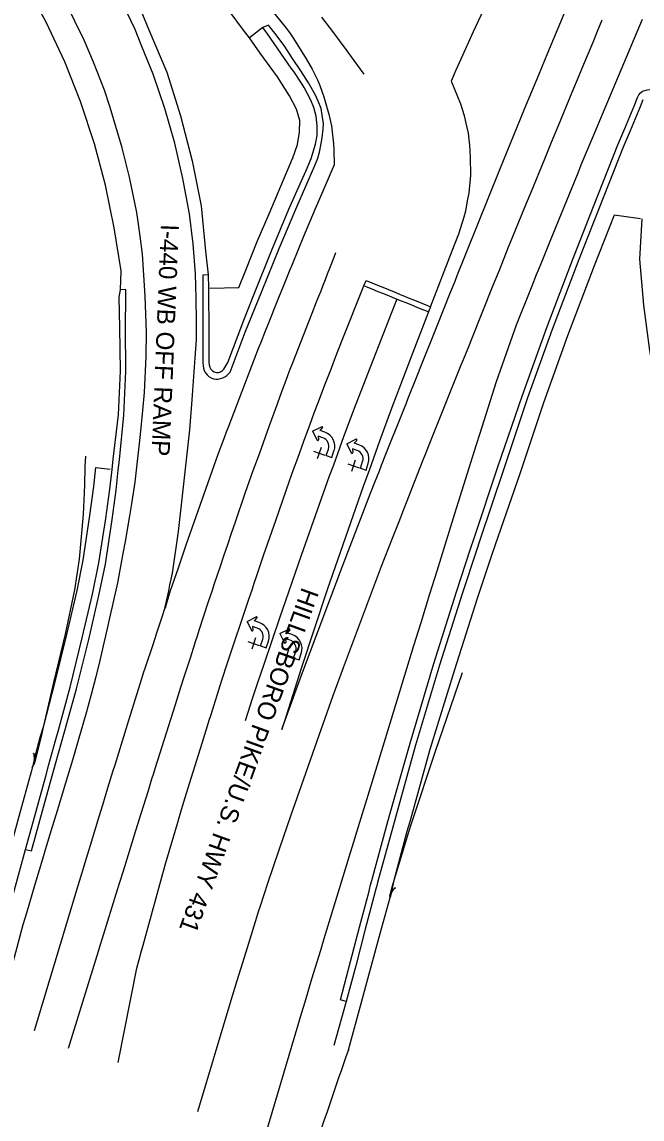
# Model space of a CAD drawing. Extents: x 1729281 to 1732101, y 650763 to 653805.
# Drawn here: x 1730319.8 to 1730526, y 652586.3 to 652950.8 of the extents above; entities that cross this region are included whole.
import ezdxf

# ---------------------------------------------------------------- set-up
doc = ezdxf.new("R2010")
doc.units = 0
for name, color, linetype in [('SURVEY - ROADSIDE BARRIERS with Text', 7, 'Continuous'), ('SURVEY - TRAFFIC CONTROL - Pavement Marking - Points - Locators', 7, 'Continuous'), ('SURVEY - TRAFFIC CONTROL - Pavement Marking with Text', 7, 'Continuous'), ('SURVEY - TRANSPORTATION - Features', 7, 'Continuous'), ('SURVEY - TRANSPORTATION - Roads', 7, 'Continuous'), ('SURVEY - TRANSPORTATION - Roads Text', 7, 'Continuous')]:
    doc.layers.add(name, color=color, linetype=linetype)

msp = doc.modelspace()

# ---------------------------------------------------------------- linework, layer by layer
at = {"layer": 'SURVEY - ROADSIDE BARRIERS with Text'}
for p, q in [((1730323.48, 652707.85), (1730323.81, 652707.7)), ((1730323.28, 652703.06), (1730323.77, 652703.93))]:
    msp.add_line(p, q, dxfattribs=at)
for points in [[(1730317.03, 652661.21), (1730321.04, 652675.83), (1730323.65, 652685.33), (1730327.77, 652700.22), (1730328.82, 652704.05), (1730331.03, 652712), (1730332.04, 652715.52), (1730335.89, 652729.8), (1730339.91, 652746.11), (1730343.31, 652760.69), (1730345.43, 652771.07), (1730347.71, 652785.85), (1730349.04, 652795.59), (1730349.79, 652802.13), (1730350.2, 652805.52), (1730351.91, 652820.29), (1730352.55, 652834.89), (1730352.42, 652849.23), (1730352.17, 652859.39), (1730352.6, 652861.75), (1730352.77, 652868.11), (1730350.46, 652882.38), (1730347.64, 652896.54), (1730343.94, 652910.3), (1730339.31, 652924.42), (1730334.05, 652937.55), (1730327.89, 652950.76), (1730321.01, 652963.38)], [(1730340.94, 652806.57), (1730340.78, 652803.16), (1730340.61, 652796.87), (1730340.24, 652787.16), (1730338.91, 652772.25), (1730337.28, 652762.07), (1730334.19, 652747.41), (1730330.32, 652731.28), (1730327.01, 652716.98), (1730326.18, 652713.41), (1730324.22, 652705.45), (1730323.77, 652703.93)], [(1730442.21, 652659.85), (1730442.15, 652660.49), (1730442.56, 652661.96), (1730442.96, 652663.41), (1730448.42, 652681.69), (1730449.44, 652684.86), (1730457.36, 652708.51), (1730466.35, 652734.7)], [(1730323.81, 652707.7), (1730323.87, 652705.55), (1730322.94, 652701.68), (1730318.83, 652686.79), (1730312.19, 652662.65), (1730309.57, 652652.97)], [(1730428.35, 652609.31), (1730432.4, 652623.88), (1730438.97, 652647.88), (1730442.21, 652659.85), (1730442.35, 652660.43), (1730442.97, 652661.84), (1730443.86, 652663.13), (1730444.13, 652663.12)]]:
    msp.add_lwpolyline(points, dxfattribs=at)
msp.add_spline([(1730428.35, 652609.31), (1730415.72, 652571.98), (1730403.87, 652531.63), (1730394.24, 652490.63), (1730385.26, 652449.43), (1730380.52, 652428.91), (1730375.36, 652408.51), (1730367.56, 652381.34), (1730359.22, 652354.31), (1730350.97, 652327.24), (1730343.49, 652299.92), (1730331.76, 652236.06), (1730325.69, 652182.09), (1730325.22, 652171.48), (1730325.45, 652160.84), (1730326.25, 652150.19), (1730327.47, 652139.56), (1730328.99, 652131.02), (1730331.3, 652122.71), (1730334.46, 652114.6), (1730338.55, 652106.68), (1730353.24, 652086.17), (1730370.71, 652068.21), (1730383.64, 652057.01), (1730397.86, 652047.48), (1730417.53, 652038.47), (1730438.22, 652032.47), (1730458.04, 652029.27), (1730477.86, 652028.54), (1730498.82, 652030.45), (1730519.65, 652035.69), (1730535.91, 652042.78), (1730550.86, 652052.24), (1730565.16, 652063.87), (1730577.86, 652077.14), (1730589.3, 652092.39), (1730598.41, 652109.02), (1730609.65, 652143.27), (1730613.44, 652158.99), (1730614.54, 652166.87), (1730614.65, 652174.72), (1730612.2, 652191.35), (1730608.22, 652207.96), (1730604.12, 652224.02), (1730598.94, 652239.77), (1730589.94, 652257.05), (1730578.5, 652272.95), (1730563.61, 652291.16), (1730547.07, 652307.62), (1730534.67, 652317.36), (1730521.92, 652326.37), (1730495.28, 652342.65), (1730480.87, 652350.64), (1730466.34, 652358.38), (1730436.7, 652372.67), (1730372.96, 652400.09)], degree=3, dxfattribs=at)
at = {"layer": 'SURVEY - TRAFFIC CONTROL - Pavement Marking - Points - Locators'}
for p, q in [((1730416.76, 652808.15), (1730420.55, 652806.86)), ((1730419.29, 652809.4), (1730418.01, 652805.61)), ((1730428.14, 652803.96), (1730431.93, 652802.68)), ((1730430.67, 652805.21), (1730429.39, 652801.43)), ((1730394.96, 652744.92), (1730398.75, 652743.64)), ((1730397.5, 652746.17), (1730396.22, 652742.38)), ((1730405.88, 652740.88), (1730409.67, 652739.6)), ((1730408.41, 652742.13), (1730407.13, 652738.34))]:
    msp.add_line(p, q, dxfattribs=at)
at = {"layer": 'SURVEY - TRAFFIC CONTROL - Pavement Marking with Text'}
for p, q in [((1730416.45, 652814.83), (1730419.48, 652816.32)), ((1730416.45, 652814.83), (1730417.95, 652811.8)), ((1730419.87, 652812.63), (1730418.34, 652813.15)), ((1730418.34, 652813.15), (1730418.42, 652811.93)), ((1730418.96, 652815.02), (1730419.77, 652815.94)), ((1730420.5, 652814.5), (1730418.96, 652815.02)), ((1730427.83, 652810.64), (1730430.86, 652812.14)), ((1730427.83, 652810.64), (1730429.33, 652807.61)), ((1730430.34, 652810.83), (1730431.15, 652811.76)), ((1730431.88, 652810.31), (1730430.34, 652810.83)), ((1730420.98, 652806.72), (1730421.72, 652808.89)), ((1730420.98, 652806.72), (1730422.85, 652806.09)), ((1730422.85, 652806.09), (1730423.58, 652808.26)), ((1730431.25, 652808.45), (1730429.71, 652808.97)), ((1730429.71, 652808.97), (1730429.8, 652807.74)), ((1730432.36, 652802.53), (1730433.1, 652804.71)), ((1730432.36, 652802.53), (1730434.23, 652801.9)), ((1730434.23, 652801.9), (1730434.96, 652804.08)), ((1730394.66, 652751.6), (1730397.68, 652753.1)), ((1730394.66, 652751.6), (1730396.15, 652748.57)), ((1730397.17, 652751.79), (1730397.98, 652752.72)), ((1730398.7, 652751.27), (1730397.17, 652751.79)), ((1730398.07, 652749.41), (1730396.54, 652749.92)), ((1730396.54, 652749.92), (1730396.62, 652748.7)), ((1730405.57, 652747.56), (1730408.6, 652749.06)), ((1730405.57, 652747.56), (1730407.07, 652744.53)), ((1730408.08, 652747.75), (1730408.89, 652748.67)), ((1730409.62, 652747.23), (1730408.08, 652747.75)), ((1730399.19, 652743.49), (1730399.92, 652745.67)), ((1730401.05, 652742.86), (1730401.79, 652745.04)), ((1730408.99, 652745.37), (1730407.45, 652745.88)), ((1730407.45, 652745.88), (1730407.54, 652744.66)), ((1730399.19, 652743.49), (1730401.05, 652742.86)), ((1730410.1, 652739.45), (1730410.84, 652741.62)), ((1730411.97, 652738.82), (1730412.7, 652741)), ((1730410.1, 652739.45), (1730411.97, 652738.82))]:
    msp.add_line(p, q, dxfattribs=at)
for points in [[(1730462.6, 652931.2), (1730464.23, 652934.85), (1730465.86, 652938.5), (1730469.98, 652947.59), (1730475.83, 652960.29), (1730480.97, 652971.11), (1730481.83, 652972.91), (1730482.06, 652973.4)], [(1730406.19, 652715.68), (1730406.87, 652717.55), (1730408.25, 652721.3), (1730412.37, 652732.56), (1730414.44, 652738.18), (1730426.36, 652769.97), (1730435.72, 652794.2), (1730437.19, 652797.91), (1730438.66, 652801.63), (1730439.39, 652803.49), (1730440.86, 652807.2), (1730443.07, 652812.77), (1730444.55, 652816.48), (1730446.78, 652822.05), (1730447.52, 652823.9), (1730448.26, 652825.76), (1730451.23, 652833.18), (1730452.71, 652836.89), (1730454.94, 652842.45), (1730455.69, 652844.3), (1730457.91, 652849.87), (1730462.34, 652861.01), (1730463.81, 652864.72), (1730464.55, 652866.58), (1730467.49, 652874.01), (1730478.69, 652901.8), (1730487.06, 652922.11), (1730491.64, 652933.19), (1730494.71, 652940.56), (1730500.09, 652953.46)], [(1730419.44, 652952.38), (1730423.1, 652947.63), (1730427.87, 652941.2), (1730430.21, 652937.96), (1730433.49, 652933.44)], [(1730378.29, 652588.82), (1730389.03, 652624.69), (1730391.39, 652632.32), (1730392.58, 652636.14), (1730394.35, 652641.86), (1730397.91, 652653.3), (1730398.5, 652655.21), (1730399.09, 652657.12), (1730400.34, 652660.91), (1730401.63, 652664.7), (1730405.5, 652676.04), (1730409.37, 652687.38), (1730410.02, 652689.27), (1730410.66, 652691.16), (1730418.62, 652713.77), (1730423.29, 652726.95), (1730426.69, 652736.34), (1730439.36, 652769.99), (1730443.02, 652779.29), (1730445.22, 652784.86), (1730446.68, 652788.58), (1730453.27, 652805.31), (1730454.01, 652807.16), (1730455.49, 652810.87), (1730465.91, 652836.83), (1730466.65, 652838.68), (1730468.14, 652842.39), (1730469.62, 652846.1), (1730476.32, 652862.79), (1730477.06, 652864.64), (1730478.55, 652868.35), (1730481.53, 652875.76), (1730483.02, 652879.47), (1730486.81, 652888.71), (1730487.57, 652890.56), (1730489.08, 652894.26), (1730493.64, 652905.35), (1730495.91, 652910.89), (1730498.19, 652916.43), (1730502.79, 652927.5), (1730505.1, 652933.03), (1730506.63, 652936.72), (1730509.7, 652944.09), (1730511.24, 652947.78), (1730512, 652949.62), (1730512.77, 652951.47)], [(1730455.63, 652856.17), (1730462.91, 652874.77), (1730465.04, 652880.37), (1730466.86, 652886.08), (1730467.37, 652888.01), (1730468.1, 652891.93), (1730468.47, 652893.9), (1730469.03, 652899.86), (1730468.99, 652905.85), (1730468.89, 652907.84), (1730468.7, 652909.83), (1730468.3, 652913.8), (1730467.86, 652915.74), (1730466.97, 652919.64), (1730465.72, 652923.43), (1730462.75, 652930.84), (1730462.6, 652931.2)], [(1730335.36, 652609.85), (1730345.25, 652642.06), (1730345.85, 652643.97), (1730347.03, 652647.79), (1730351.18, 652661.14), (1730352.36, 652664.96), (1730353.55, 652668.77), (1730357.69, 652682.13), (1730359.48, 652687.84), (1730361.86, 652695.46), (1730363.06, 652699.28), (1730363.65, 652701.18), (1730364.25, 652703.09), (1730370.84, 652724.04), (1730372.68, 652729.74), (1730373.9, 652733.54), (1730375.74, 652739.24), (1730376.96, 652743.04), (1730377.57, 652744.94), (1730378.19, 652746.84), (1730378.8, 652748.74), (1730381.86, 652758.25), (1730383.14, 652762.03), (1730383.78, 652763.92), (1730385.06, 652767.71), (1730385.7, 652769.6), (1730386.98, 652773.38), (1730388.26, 652777.16), (1730389.54, 652780.95), (1730390.82, 652784.73), (1730394.02, 652794.19), (1730394.66, 652796.08), (1730396.03, 652799.83), (1730396.71, 652801.71), (1730398.76, 652807.34), (1730402.18, 652816.72), (1730404.91, 652824.23), (1730406.28, 652827.98), (1730407.65, 652831.74), (1730408.33, 652833.61), (1730409.04, 652835.48), (1730409.77, 652837.34), (1730416.34, 652854.07), (1730417.8, 652857.79), (1730418.53, 652859.65), (1730419.26, 652861.51), (1730419.99, 652863.37), (1730420.71, 652865.23), (1730421.44, 652867.09), (1730422.17, 652868.95), (1730423.63, 652872.67), (1730424.23, 652874.19)], [(1730433.49, 652863.11), (1730434.3, 652864.9), (1730436.15, 652864.14), (1730438, 652863.39), (1730439.85, 652862.63), (1730441.7, 652861.87), (1730443.55, 652861.11), (1730445.4, 652860.36), (1730447.25, 652859.6), (1730449.1, 652858.84), (1730450.95, 652858.09), (1730452.8, 652857.33), (1730454.65, 652856.57), (1730455.63, 652856.17)], [(1730351.79, 652605.03), (1730358.07, 652636.39), (1730359.63, 652642.17), (1730360.16, 652644.1), (1730367.51, 652671.08), (1730371.52, 652684.48), (1730372.66, 652688.31), (1730373.24, 652690.22), (1730374.95, 652695.96), (1730379.72, 652711.21), (1730381.52, 652716.92), (1730382.12, 652718.83), (1730382.72, 652720.73), (1730386.34, 652732.15), (1730388.22, 652737.84), (1730395.16, 652758.69), (1730396.44, 652762.47), (1730397.08, 652764.36), (1730397.72, 652766.26), (1730400.29, 652773.82), (1730404.2, 652785.15), (1730408.8, 652798.35), (1730410.17, 652802.1), (1730411.54, 652805.86), (1730412.22, 652807.74), (1730413.58, 652811.49), (1730415.63, 652817.12), (1730417, 652820.88), (1730418.42, 652824.61), (1730420.57, 652830.2), (1730422.71, 652835.8), (1730423.43, 652837.66), (1730424.86, 652841.39), (1730426.33, 652845.1), (1730433.49, 652863.11)], [(1730455.63, 652856.17), (1730454.99, 652854.45), (1730453.13, 652855.2), (1730451.28, 652855.95), (1730449.42, 652856.69), (1730447.57, 652857.44), (1730445.72, 652858.19), (1730443.86, 652858.93), (1730442.01, 652859.68), (1730440.15, 652860.43), (1730438.3, 652861.17), (1730436.44, 652861.92), (1730434.59, 652862.67), (1730433.49, 652863.11)], [(1730394.13, 652718.75), (1730396.63, 652726.34), (1730398.51, 652732.03), (1730399.14, 652733.92), (1730400.42, 652737.7), (1730405.54, 652752.84), (1730412.73, 652773.6), (1730419.37, 652792.44), (1730420.06, 652794.32), (1730422.11, 652799.95), (1730423.48, 652803.7), (1730424.84, 652807.45), (1730426.21, 652811.21), (1730426.9, 652813.08), (1730430.4, 652822.43), (1730433.3, 652829.88), (1730442.75, 652854.07), (1730444.61, 652858.82)], [(1730454.99, 652854.45), (1730449.19, 652839.56), (1730445.66, 652830.21), (1730442.84, 652822.74), (1730438.73, 652811.48), (1730437.37, 652807.73), (1730436.01, 652803.97), (1730435.33, 652802.09), (1730433.29, 652796.46), (1730421.47, 652762.5), (1730412.64, 652735.97), (1730408.4, 652722.64), (1730407.19, 652718.84), (1730406.59, 652716.93), (1730406.19, 652715.68)], [(1730323.98, 652615.7), (1730338.49, 652663.91), (1730340.25, 652669.64), (1730340.83, 652671.55), (1730342.59, 652677.28), (1730345.51, 652686.83), (1730346.68, 652690.65), (1730348.44, 652696.37), (1730350.2, 652702.1), (1730350.8, 652704), (1730354.94, 652717.35), (1730359.68, 652732.6), (1730360.3, 652734.5), (1730360.93, 652736.4), (1730363.43, 652743.98), (1730364.68, 652747.78), (1730366.56, 652753.46), (1730367.37, 652755.91)]]:
    msp.add_lwpolyline(points, dxfattribs=at)
for centre, radius, start, end in [((1730419.59, 652816.1), 0.246, 318.8855, 116.3337), ((1730418.92, 652809.84), 4.92, 341.3337, 71.3337), ((1730418.17, 652811.91), 0.246, 206.3337, 3.8269), ((1730418.92, 652809.84), 2.95, 341.3337, 71.3337), ((1730430.97, 652811.92), 0.246, 318.8855, 116.3337), ((1730430.3, 652805.65), 4.92, 341.3337, 71.3337), ((1730429.55, 652807.72), 0.246, 206.3337, 3.8269), ((1730430.3, 652805.65), 2.95, 341.3337, 71.3337), ((1730397.79, 652752.88), 0.246, 318.8855, 116.3337), ((1730397.12, 652746.61), 4.92, 341.3337, 71.3337), ((1730396.37, 652748.68), 0.246, 206.3337, 3.8269), ((1730397.12, 652746.61), 2.95, 341.3337, 71.3337), ((1730408.71, 652748.84), 0.246, 318.8855, 116.3337), ((1730407.29, 652744.64), 0.246, 206.3337, 3.8269), ((1730408.04, 652742.57), 2.95, 341.3337, 71.3337), ((1730408.04, 652742.57), 4.92, 341.3337, 71.3337)]:
    msp.add_arc(centre, radius, start, end, dxfattribs=at)
at = {"layer": 'SURVEY - TRANSPORTATION - Features'}
for points in [[(1730242.84, 653062.34), (1730256.85, 653056.28), (1730270.49, 653049.39), (1730283.61, 653041.79), (1730296.37, 653033.41), (1730308.39, 653023.98), (1730319.79, 653013.43), (1730330.32, 653002.12), (1730338.26, 652992.05), (1730340.57, 652988.7), (1730348.86, 652975.48), (1730356.23, 652962.2), (1730362.05, 652948.14), (1730367.97, 652934.08), (1730372.53, 652919.59), (1730376.43, 652904.68), (1730379.45, 652889.74), (1730380.84, 652874.59), (1730381.75, 652866.73)], [(1730395.47, 652945.52), (1730393.84, 652947.63), (1730383.29, 652961.88), (1730377.65, 652957.37)], [(1730386.94, 652835.44), (1730388.28, 652837.64), (1730393.65, 652851.71), (1730397.2, 652860.68), (1730402.85, 652874.72), (1730408.57, 652888.57), (1730414.62, 652902.27), (1730415.98, 652905.38), (1730417.42, 652910.21), (1730417.93, 652913.04), (1730418, 652916.31), (1730417.62, 652919.48), (1730416.9, 652922.4), (1730415.93, 652924.82), (1730413.71, 652929.02), (1730412.8, 652930.47), (1730410.27, 652934.29), (1730409.37, 652935.48), (1730401.5, 652946.83), (1730399.9, 652948.94)], [(1730389.02, 652834.42), (1730394.02, 652847.69), (1730399.74, 652861.53), (1730405.39, 652875.53), (1730411.2, 652889.34), (1730417.25, 652903.05), (1730418.23, 652905.5), (1730418.78, 652907.57), (1730419.36, 652910.4), (1730419.7, 652912.3), (1730419.97, 652915.17), (1730420.11, 652917.08), (1730419.69, 652919.87), (1730419.27, 652922.02), (1730418.37, 652924.44), (1730417.48, 652926.44), (1730415.13, 652930.55), (1730412.59, 652934.58), (1730409.79, 652938.64), (1730407.18, 652942.68), (1730404.32, 652946.57), (1730401.81, 652949.74), (1730399.9, 652948.94), (1730399.43, 652948.58), (1730395.47, 652945.52)], [(1730382.31, 652862.32), (1730391.91, 652862.53), (1730394.22, 652868.38), (1730398.09, 652877.87), (1730402.02, 652887.06), (1730405.92, 652896.25), (1730409.79, 652905.45), (1730409.77, 652905.34), (1730411.43, 652910.11), (1730412.09, 652914.21), (1730412.18, 652918.01), (1730411.14, 652921.82), (1730408.81, 652926.29), (1730404.79, 652932.52), (1730399.03, 652940.38), (1730395.47, 652945.52)], [(1730524.52, 652925.72), (1730524.94, 652926.61), (1730525.5, 652927.25), (1730526.17, 652927.75), (1730526.93, 652928.06), (1730527.69, 652928.21), (1730528.44, 652928.31), (1730529.19, 652928.28), (1730529.91, 652928.11), (1730530.55, 652927.77), (1730531.14, 652927.37), (1730531.67, 652926.89), (1730532.11, 652926.33), (1730532.49, 652925.71), (1730533.77, 652923.61)], [(1730526.31, 652924.97), (1730525.34, 652922.61), (1730522, 652914.67), (1730519.75, 652909.24), (1730511.61, 652888.73), (1730505, 652871.87), (1730496.11, 652848.62), (1730487.95, 652825.93), (1730480, 652802.33), (1730472.07, 652778.64), (1730470.91, 652775.13), (1730466.22, 652760.83), (1730458.62, 652737.08), (1730450.72, 652710.55), (1730443.99, 652686.52), (1730443.09, 652683.31), (1730438.07, 652664.91), (1730437.67, 652663.46), (1730437.3, 652661.97), (1730437.15, 652661.4), (1730433.98, 652649.41), (1730430.87, 652637.21), (1730427.62, 652625.31), (1730423.53, 652610.75)], [(1730427.62, 652625.31), (1730425.73, 652625.88), (1730429.12, 652638.63), (1730432.09, 652649.99), (1730435.24, 652661.98), (1730435.39, 652662.56), (1730435.76, 652664.05), (1730436.16, 652665.49), (1730441.19, 652683.89), (1730442.07, 652687.1), (1730448.86, 652711.12), (1730456.77, 652737.65), (1730464.36, 652761.41), (1730469, 652775.72), (1730470.15, 652779.25), (1730478.09, 652802.93), (1730486.18, 652826.5), (1730494.38, 652849.31), (1730503.25, 652872.58), (1730509.86, 652889.44), (1730517.92, 652910), (1730520.22, 652915.42), (1730523.56, 652923.36), (1730524.52, 652925.72)], [(1730525.5, 652885.4), (1730516.73, 652886.64), (1730510.11, 652869.78), (1730501.24, 652846.56), (1730493.25, 652824.26), (1730485.31, 652800.68), (1730477.11, 652777.06), (1730475.91, 652773.56), (1730471.22, 652759.27), (1730463.62, 652735.54), (1730455.47, 652709.09), (1730448.75, 652685.07), (1730447.85, 652681.86)], [(1730678.59, 652584.69), (1730668.21, 652595.62), (1730658.07, 652606.65), (1730647.69, 652617.44), (1730637.8, 652628.92), (1730628.07, 652640.33), (1730618.44, 652652.06), (1730609.31, 652663.93), (1730600.32, 652676.19), (1730591.81, 652688.51), (1730583.64, 652701.32), (1730575.8, 652714.39), (1730568.39, 652727.49), (1730561.54, 652740.88), (1730555.14, 652754.59), (1730549.5, 652768.71), (1730543.86, 652782.81), (1730539.06, 652797.2), (1730534.94, 652811.81), (1730531.23, 652826.55), (1730528.6, 652841.6), (1730526.57, 652856.7), (1730525.29, 652872.01), (1730526.01, 652885.35)], [(1730381.75, 652866.73), (1730379.93, 652866.69), (1730379.96, 652851.57), (1730379.95, 652837.67), (1730380.03, 652836.56)], [(1730381.75, 652866.73), (1730381.86, 652862.3), (1730381.99, 652847.08), (1730381.97, 652837.7), (1730382.07, 652836.87)], [(1730337.98, 652729.24), (1730342.02, 652745.63), (1730345.43, 652760.21), (1730347.56, 652770.69), (1730349.84, 652785.47), (1730351.17, 652795.26), (1730351.85, 652801.9), (1730352.26, 652805.29), (1730353.73, 652820.11), (1730354.38, 652834.8), (1730354.26, 652849.28), (1730354.32, 652859.54), (1730354.37, 652861.87), (1730352.6, 652861.75)], [(1730380.03, 652836.56), (1730380.2, 652835.74), (1730380.47, 652834.95), (1730380.87, 652834.22), (1730381.41, 652833.58), (1730382.01, 652833), (1730382.7, 652832.54), (1730383.47, 652832.21), (1730384.29, 652832.08), (1730385.11, 652832.14), (1730385.88, 652832.33), (1730386.62, 652832.59), (1730387.3, 652832.93), (1730387.95, 652833.34), (1730388.54, 652833.83), (1730389.02, 652834.42)], [(1730382.07, 652836.87), (1730382.34, 652836.08), (1730382.67, 652835.44), (1730383.14, 652834.89), (1730383.77, 652834.51), (1730384.48, 652834.32), (1730385.2, 652834.35), (1730385.88, 652834.55), (1730386.46, 652834.94), (1730386.94, 652835.44)], [(1730323.87, 652705.55), (1730326.04, 652713.45), (1730327.06, 652716.97), (1730330.81, 652731.15), (1730334.78, 652747.28), (1730338.17, 652761.86), (1730340.23, 652772.01), (1730342.4, 652786.78), (1730343.71, 652796.4), (1730344.43, 652802.74), (1730349.2, 652802.2)], [(1730321.04, 652675.83), (1730322.96, 652675.41), (1730326.95, 652689.87), (1730331.01, 652704.29), (1730333.01, 652711.42), (1730333.99, 652714.95), (1730337.98, 652729.24)], [(1730447.85, 652681.86), (1730443.42, 652665.49), (1730442.21, 652659.85)]]:
    msp.add_lwpolyline(points, dxfattribs=at)
at = {"layer": 'SURVEY - TRANSPORTATION - Roads'}
for points in [[(1730385.19, 652976.62), (1730390.46, 652970.6), (1730397.86, 652961.16), (1730404.04, 652953.3), (1730407.74, 652948.58), (1730408.98, 652947.01), (1730410.08, 652945.35), (1730414.32, 652938.57), (1730416.33, 652935.1), (1730417.24, 652933.33), (1730418.1, 652931.52), (1730418.91, 652929.69), (1730420.24, 652925.92), (1730421.36, 652922.08), (1730421.91, 652920.16), (1730422.75, 652916.25), (1730423.43, 652910.3), (1730423.58, 652908.3), (1730423.67, 652903.38)], [(1730367.37, 652755.91), (1730368.2, 652759.82), (1730368.62, 652761.77), (1730369.04, 652763.72), (1730369.45, 652765.68), (1730369.87, 652767.63), (1730371.87, 652781.47), (1730372.99, 652791.4), (1730373.44, 652795.37), (1730375.01, 652809.27), (1730375.6, 652815.23), (1730376.39, 652825.2), (1730377.43, 652839.15), (1730377.82, 652845.14), (1730377.84, 652851.14), (1730377.77, 652859.14), (1730377.51, 652867.13), (1730376.77, 652877.11), (1730375.51, 652887.03), (1730373.37, 652898.83), (1730370.67, 652910.52), (1730367.31, 652922.04), (1730363.47, 652933.41), (1730359.71, 652942.68), (1730357.45, 652948.24), (1730350.64, 652962.71)], [(1730199.26, 652195.15), (1730320.26, 652650.92), (1730321.41, 652654.74), (1730324.26, 652664.32), (1730327.11, 652673.89), (1730327.69, 652675.8), (1730330.01, 652683.45), (1730331.75, 652689.18), (1730334.65, 652698.74), (1730336.4, 652704.47), (1730337.51, 652708.3), (1730338.63, 652712.13), (1730341.42, 652721.72), (1730342.98, 652727.5), (1730344.51, 652733.29), (1730345.54, 652737.15), (1730346.44, 652741.04), (1730347.32, 652744.94), (1730347.77, 652746.88), (1730349.54, 652754.67), (1730349.99, 652756.62), (1730350.43, 652758.57), (1730351.76, 652764.41), (1730353.54, 652774.24), (1730354.24, 652778.17), (1730355.62, 652786.04), (1730356.22, 652789.99), (1730357.43, 652797.89), (1730359.23, 652813.78), (1730360.02, 652821.73), (1730360.54, 652827.71), (1730361.15, 652839.69), (1730361.22, 652847.68), (1730361.06, 652853.68), (1730360.81, 652859.67), (1730359.88, 652873.64), (1730359.11, 652879.59), (1730358.57, 652883.56), (1730358.04, 652887.52), (1730355.63, 652899.28), (1730353.16, 652908.96), (1730349.14, 652922.38), (1730347.32, 652928.09), (1730343.64, 652937.39), (1730340.49, 652944.74), (1730334.36, 652957.33)], [(1730525.99, 652951.61), (1730513.59, 652922.15), (1730511.28, 652916.62), (1730510.51, 652914.78), (1730505.91, 652903.72), (1730504.4, 652900.02), (1730499.11, 652887.08), (1730495.33, 652877.83), (1730493.07, 652872.28), (1730492.31, 652870.43), (1730491.56, 652868.58), (1730490.81, 652866.73), (1730489.32, 652863.02), (1730484.13, 652850.04), (1730483.45, 652848.17), (1730477.46, 652831.21), (1730472.03, 652814.07), (1730470.85, 652810.26), (1730463.69, 652787.38), (1730459.51, 652774.04), (1730457.72, 652768.32), (1730455.34, 652760.69), (1730452.41, 652751.14), (1730450.06, 652743.5), (1730447.71, 652735.87), (1730445.36, 652728.23), (1730436.56, 652699.59), (1730430.73, 652680.48), (1730430.15, 652678.57), (1730428.98, 652674.75), (1730424.88, 652661.38), (1730420.21, 652646.1), (1730419.05, 652642.28), (1730416.15, 652632.72), (1730413.85, 652625.07), (1730412.7, 652621.24), (1730412.13, 652619.33), (1730411.55, 652617.42), (1730400.77, 652581.22)], [(1730423.67, 652903.38), (1730422.88, 652901.54), (1730421.29, 652897.88), (1730417.34, 652888.7), (1730413.44, 652879.51), (1730409.68, 652870.26), (1730408.92, 652868.41), (1730406.66, 652862.86), (1730405.16, 652859.17), (1730401.42, 652849.91), (1730400.69, 652848.05), (1730399.24, 652844.33), (1730398.51, 652842.47), (1730397.05, 652838.75), (1730392.01, 652825.72), (1730388.46, 652816.39), (1730387.75, 652814.52), (1730387.04, 652812.65), (1730384.99, 652807.03), (1730380.93, 652795.75), (1730379.6, 652791.98), (1730378.28, 652788.22), (1730375.63, 652780.68), (1730374.97, 652778.8), (1730374.32, 652776.91), (1730371.74, 652769.35), (1730369.16, 652761.79), (1730367.98, 652757.97), (1730367.41, 652756.06), (1730367.37, 652755.91)]]:
    msp.add_lwpolyline(points, dxfattribs=at)

# ---------------------------------------------------------------- texts
at = {"layer": 'SURVEY - TRANSPORTATION - Roads Text'}
for s, rotation, p in [('I-440 WB OFF RAMP', 267.6567, (1730366.05, 652883.68)), ('I-440 WB OFF RAMP', 267.6567, (1730366.05, 652883.68)), ('HILLSBORO PIKE/U.S. HWY 431', 250.1754, (1730412.99, 652763.22))]:
    msp.add_text(s, height=6, rotation=rotation, dxfattribs=at).set_placement(p)

doc.saveas('drawing.dxf')
